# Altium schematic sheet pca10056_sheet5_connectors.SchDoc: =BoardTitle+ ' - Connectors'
size A3; Organization: Nordic Semiconductor; DocumentNumber: 5; SheetNumber: 5; SheetTotal: 6; CompanyName: Nordic Semiconductor; DocumentSize: A3
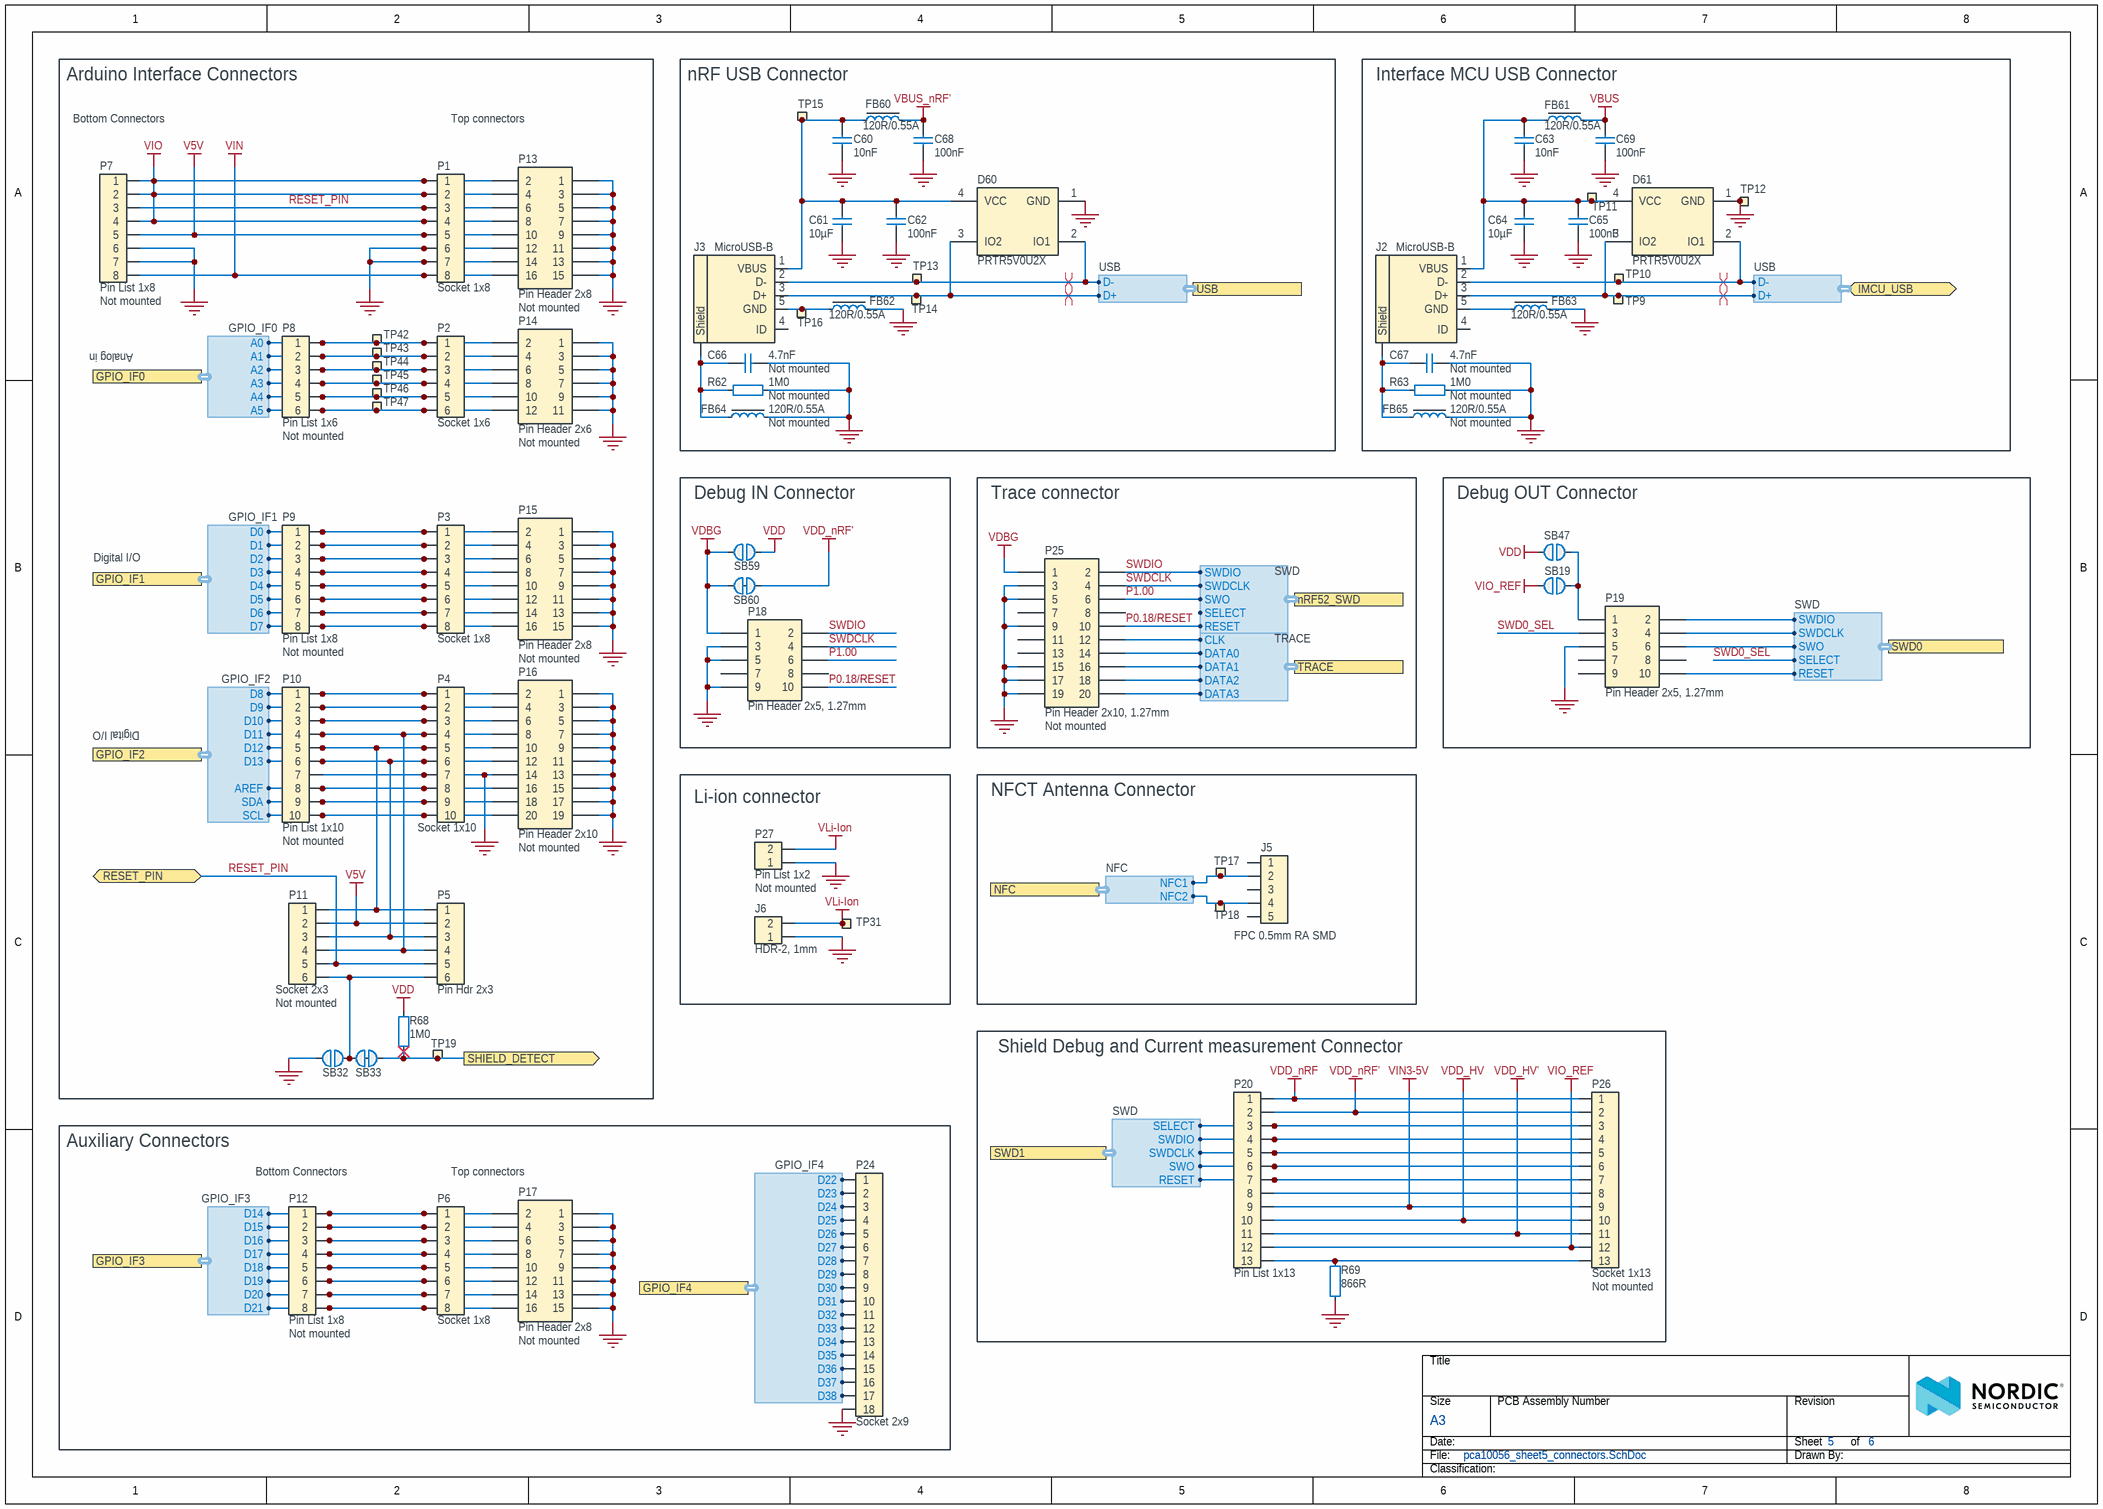
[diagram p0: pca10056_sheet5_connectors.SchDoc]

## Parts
C60  10nF  [CAPC0603X03L_C]
C61  10µF  [CAPC1608X06L]
C62  100nF  [CAPC0603X03L_C]
C63  10nF  [CAPC0603X03L_C]
C64  10µF  [CAPC1608X06L]
C65  100nF  [CAPC0603X03L_C]
C66  4.7nF  Assembly: Not mounted  [CAPC0603X03L_C]
C67  4.7nF  Assembly: Not mounted  [CAPC0603X03L_C]
C68  100nF  [CAPC0603X03L_C]
C69  100nF  [CAPC0603X03L_C]
D60  PRTR5V0U2X  [SOT190P230X110-4L]
D61  PRTR5V0U2X  [SOT190P230X110-4L]
FB60  120R/0.55A  [INDC1005X04L]
FB61  120R/0.55A  [INDC1005X04L]
FB62  120R/0.55A  [INDC1005X04L]
FB63  120R/0.55A  [INDC1005X04L]
FB64  120R/0.55A  Assembly: Not mounted  [INDC1005X04L]
FB65  120R/0.55A  Assembly: Not mounted  [INDC1005X04L]
J2  MicroUSB-B  [USB-Micro-B-RA-SMD-PiP_Allen]
J3  MicroUSB-B  [USB-Micro-B-RA-SMD-PiP_Allen]
J5  FPC 0.5mm RA SMD  [FPC_05P-0.5mm-RA-SMD]
J6  HDR-2, 1mm  [SM02B-SRSS-TB]
P1  Socket 1x8  [SOCKET_1x8_SMD]
P2  Socket 1x6  [SOCKET_1x6_SMD]
P3  Socket 1x8  [SOCKET_1x8_SMD]
P4  Socket 1x10  [SOCKET_1x10_SMD]
P5  Pin Hdr 2x3  [HDR_2x3-SMD]
P6  Socket 1x8  [SOCKET_1x8_SMD]
P7  Pin List 1x8  Assembly: Not mounted  [LIST_1x8_SMD-NC]
P8  Pin List 1x6  Assembly: Not mounted  [LIST_1x6_SMD-NC]
P9  Pin List 1x8  Assembly: Not mounted  [LIST_1x8_SMD-NC]
P10  Pin List 1x10  Assembly: Not mounted  [LIST_1x10_SMD-NC]
P11  Socket 2x3  Assembly: Not mounted  [SOCKET_2x3_SMD-2.54mm-NC]
P12  Pin List 1x8  Assembly: Not mounted  [LIST_1x8_SMD-NC]
P13  Pin Header 2x8  Assembly: Not mounted  [HDR_2x8-NC]
P14  Pin Header 2x6  Assembly: Not mounted  [HDR_2x6-NC]
P15  Pin Header 2x8  Assembly: Not mounted  [HDR_2x8-NC]
P16  Pin Header 2x10  Assembly: Not mounted  [HDR_2x10-NC]
P17  Pin Header 2x8  Assembly: Not mounted  [HDR_2x8-NC]
P18  Pin Header 2x5, 1.27mm  [HDR_2x5-SMD-1.27mm-K]
P19  Pin Header 2x5, 1.27mm  [HDR_2x5-SMD-1.27mm-K]
P20  Pin List 1x13  [LIST_1x13_SMD]
P24  Socket 2x9  [SOCKET_2x9_SMD-2.54mm-Mirrored]
P25  Pin Header 2x10, 1.27mm  Assembly: Not mounted  [HDR_2x10-SMD-1.27mm-NC]
P26  Socket 1x13  Assembly: Not mounted  [LIST_1x13_SMD-NC]
P27  Pin List 1x2  Assembly: Not mounted  [LIST_1x2-NC]
R62  1M0  Assembly: Not mounted  [RESC0603X03L_C]
R63  1M0  Assembly: Not mounted  [RESC0603X03L_C]
R68  1M0  [RESC0603X03L_C]
R69  866R  [RESC0603X03L_C]
SB19  Solderbridge  [Solderbridge]  (value not drawn)  (no BOM)
SB32  Solderbridge  [Solderbridge]  (value not drawn)  (no BOM)
SB33  Solderbridge  [Solderbridge_Shorted]  (value not drawn)  (net tie, no BOM)
SB47  Solderbridge  [Solderbridge]  (value not drawn)  (no BOM)
SB59  Solderbridge  [Solderbridge]  (value not drawn)  (no BOM)
SB60  Solderbridge  [Solderbridge_Shorted]  (value not drawn)  (net tie, no BOM)
TP9  Ø1.0mm,SMD  [TP_SMD_D1.0mm]  (value not drawn)  (no BOM)
TP10  Ø1.0mm,SMD  [TP_SMD_D1.0mm]  (value not drawn)  (no BOM)
TP11  Ø1.0mm,SMD  [TP_SMD_D1.0mm]  (value not drawn)  (no BOM)
TP12  Ø1.0mm,SMD  [TP_SMD_D1.0mm]  (value not drawn)  (no BOM)
TP13  Ø1.5mm,SMD  [TP_SMD_D1.5mm]  (value not drawn)  (no BOM)
TP14  Ø1.5mm,SMD  [TP_SMD_D1.5mm]  (value not drawn)  (no BOM)
TP15  Ø1.5mm,SMD  [TP_SMD_D1.5mm]  (value not drawn)  (no BOM)
TP16  Ø1.5mm,SMD  [TP_SMD_D1.5mm]  (value not drawn)  (no BOM)
TP17  Ø1.0mm,SMD  [TP_SMD_D1.0mm]  (value not drawn)  (no BOM)
TP18  Ø1.0mm,SMD  [TP_SMD_D1.0mm]  (value not drawn)  (no BOM)
TP19  Ø1.0mm,SMD  [TP_SMD_D1.0mm]  (value not drawn)  (no BOM)
TP31  Ø1.0mm,SMD  [TP_SMD_D1.0mm]  (value not drawn)  (no BOM)
TP42  Ø1.0mm,SMD  [TP_SMD_D1.0mm]  (value not drawn)  (no BOM)
TP43  Ø1.0mm,SMD  [TP_SMD_D1.0mm]  (value not drawn)  (no BOM)
TP44  Ø1.0mm,SMD  [TP_SMD_D1.0mm]  (value not drawn)  (no BOM)
TP45  Ø1.0mm,SMD  [TP_SMD_D1.0mm]  (value not drawn)  (no BOM)
TP46  Ø1.0mm,SMD  [TP_SMD_D1.0mm]  (value not drawn)  (no BOM)
TP47  Ø1.0mm,SMD  [TP_SMD_D1.0mm]  (value not drawn)  (no BOM)

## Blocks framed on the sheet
Arduino Interface Connectors: P1-P5 P7-P11 P13-P16 R68 SB32 SB33 TP19 TP42-TP47
nRF USB Connector: C60-C62 C66 C68 D60 FB60 FB62 FB64 J3 R62 TP13-TP16
Interface MCU USB Connector: C63-C65 C67 C69 D61 FB61 FB63 FB65 J2 R63 TP9-TP12
Debug IN Connector: P18 SB59 SB60
Trace connector: P25
Debug OUT Connector: P19 SB19 SB47
Li-ion connector: J6 P27 TP31
NFCT Antenna Connector: J5 TP17 TP18
Shield Debug and Current measurement Connector: P20 P26 R69
Auxiliary Connectors: P6 P12 P17 P24

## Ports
GPIO_IF0 (harness GPIO_IF0), GPIO_IF1 (harness GPIO_IF1), GPIO_IF2 (harness GPIO_IF2), GPIO_IF3 (harness GPIO_IF3), GPIO_IF4 (harness GPIO_IF4), IMCU_USB (bidir, harness USB), NFC (harness NFC), nRF52_SWD (harness SWD), RESET_PIN (bidir), SHIELD_DETECT (out), SWD0 (harness SWD), SWD1 (harness SWD), TRACE (harness TRACE), USB (harness USB)

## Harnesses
USB: D-, D+
USB: D+, D-
SWD: SWDIO, SWDCLK, SWO, RESET, SELECT
TRACE: CLK, DATA0, DATA1, DATA3, DATA2
NFC: NFC2, NFC1
GPIO_IF4: D22, D23, D24, D25, D26, D27, D28, D29, D30, D31, D32, D33, D34, D35, D36, D37, D38
GPIO_IF3: D14, D15, D16, D17, D18, D19, D20, D21
GPIO_IF1: D0, D1, D2, D3, D4, D5, D6, D7
GPIO_IF2: D8, D9, D10, D11, D12, D13, AREF, SDA, SCL
GPIO_IF0: A0, A1, A2, A3, A4, A5

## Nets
GND: C60.1 C61.1 C62.1 C63.2 C64.1 C65.1 C66.1 C67.1 C68.1 C69.1 D60.1(GND) D61.1(GND) FB62.2 FB63.2 FB64.2 FB65.2 J6.1 P1.6 P1.7 P4.7 P7.6 P7.7 P10.7 P13.1 P13.3 P13.5 P13.7 P13.9 P13.11 P13.12 P13.13 P13.14 P13.15 P14.1 P14.3 P14.5 P14.7 P14.9 P14.11 P15.1 P15.3 P15.5 P15.7 P15.9 P15.11 P15.13 P15.15 P16.1 P16.3 P16.5 P16.7 P16.9 P16.11 P16.13 P16.14 P16.15 P16.17 P16.19 P17.1 P17.3 P17.5 P17.7 P17.9 P17.11 P17.13 P17.15 P18.3 P18.5 P18.9 P19.5 P24.18 P25.3 P25.5 P25.9 P25.15 P25.17 P25.19 P27.1 R62.1 R63.1 R69.1 SB32.1 TP12.1
V5V: P1.5 P5.2 P7.5 P11.2 P13.10
VBUS: C69.2 FB61.2
VBUS_nRF': C68.2 FB60.2
VDBG: P18.1 P25.1 SB59.1 SB60.1
VDD: R68.2 SB47.1 SB59.2
VDD_HV: P20.10 P26.10
VDD_HV': P20.11 P26.11
VDD_nRF: P20.1 P26.1
VDD_nRF': P20.2 P26.2 SB60.2
VIN: P1.8 P7.8 P13.16
VIN3-5V: P20.9 P26.9
VIO: P1.1 P1.2 P1.4 P7.1 P7.2 P7.4 P13.2 P13.4 P13.8
VIO_REF: P20.12 P26.12 SB19.2
VLi-Ion: J6.2 P27.2 TP31.1
P0.18/RESET: P18.10 P25.10 ; port nRF52_SWD.RESET
P1.00: P18.6 P25.6 ; port nRF52_SWD.SWO
RESET_PIN: P1.3 P5.5 P7.3 P11.5 P13.6 ; port RESET_PIN
SHIELD_DETECT: R68.1 SB33.2 TP19.1 ; port SHIELD_DETECT
SWD0_SEL: P19.3 ; port SWD0.SELECT
SWDCLK: P18.4 P25.4 ; port nRF52_SWD.SWDCLK
SWDIO: P18.2 P25.2 ; port nRF52_SWD.SWDIO
NetC60_2: C60.2 C61.2 C62.2 D60.4(VCC) FB60.1 J3.1(VBUS) TP15.1
NetC63_1: C63.1 C64.2 C65.2 D61.4(VCC) FB61.1 J2.1(VBUS) TP11.1
NetC66_2: C66.2 FB64.1 J3.6(Shield) R62.2
NetC67_2: C67.2 FB65.1 J2.6(Shield) R63.2
NetD60_2: D60.2(IO1) J3.2(D-) TP13.1 ; port USB.D-
NetD60_3: D60.3(IO2) J3.3(D+) TP14.1 ; port USB.D+
NetD61_2: D61.2(IO1) J2.2(D-) TP10.1 ; port IMCU_USB.D-
NetD61_3: D61.3(IO2) J2.3(D+) TP9.1 ; port IMCU_USB.D+
NetFB62_1: FB62.1 J3.5(GND) TP16.1
NetFB63_1: FB63.1 J2.5(GND)
NetJ5_2: J5.2 TP17.1 ; port NFC.NFC1
NetJ5_4: J5.4 TP18.1 ; port NFC.NFC2
NetP2_1: P2.1 P8.1 P14.2 TP42.1 ; port GPIO_IF0.A0
NetP2_2: P2.2 P8.2 P14.4 TP43.1 ; port GPIO_IF0.A1
NetP2_3: P2.3 P8.3 P14.6 TP44.1 ; port GPIO_IF0.A2
NetP2_4: P2.4 P8.4 P14.8 TP45.1 ; port GPIO_IF0.A3
NetP2_5: P2.5 P8.5 P14.10 TP46.1 ; port GPIO_IF0.A4
NetP2_6: P2.6 P8.6 P14.12 TP47.1 ; port GPIO_IF0.A5
NetP3_1: P3.1 P9.1 P15.2 ; port GPIO_IF1.D0
NetP3_2: P3.2 P9.2 P15.4 ; port GPIO_IF1.D1
NetP3_3: P3.3 P9.3 P15.6 ; port GPIO_IF1.D2
NetP3_4: P3.4 P9.4 P15.8 ; port GPIO_IF1.D3
NetP3_5: P3.5 P9.5 P15.10 ; port GPIO_IF1.D4
NetP3_6: P3.6 P9.6 P15.12 ; port GPIO_IF1.D5
NetP3_7: P3.7 P9.7 P15.14 ; port GPIO_IF1.D6
NetP3_8: P3.8 P9.8 P15.16 ; port GPIO_IF1.D7
NetP4_1: P4.1 P10.1 P16.2 ; port GPIO_IF2.D8
NetP4_2: P4.2 P10.2 P16.4 ; port GPIO_IF2.D9
NetP4_3: P4.3 P10.3 P16.6 ; port GPIO_IF2.D10
NetP4_4: P4.4 P5.4 P10.4 P11.4 P16.8 ; port GPIO_IF2.D11
NetP4_5: P4.5 P5.1 P10.5 P11.1 P16.10 ; port GPIO_IF2.D12
NetP4_6: P4.6 P5.3 P10.6 P11.3 P16.12 ; port GPIO_IF2.D13
NetP4_8: P4.8 P10.8 P16.16 ; port GPIO_IF2.AREF
NetP4_9: P4.9 P10.9 P16.18 ; port GPIO_IF2.SDA
NetP4_10: P4.10 P10.10 P16.20 ; port GPIO_IF2.SCL
NetP5_6: P5.6 P11.6 SB32.2 SB33.1
NetP6_1: P6.1 P12.1 P17.2 ; port GPIO_IF3.D14
NetP6_2: P6.2 P12.2 P17.4 ; port GPIO_IF3.D15
NetP6_3: P6.3 P12.3 P17.6 ; port GPIO_IF3.D16
NetP6_4: P6.4 P12.4 P17.8 ; port GPIO_IF3.D17
NetP6_5: P6.5 P12.5 P17.10 ; port GPIO_IF3.D18
NetP6_6: P6.6 P12.6 P17.12 ; port GPIO_IF3.D19
NetP6_7: P6.7 P12.7 P17.14 ; port GPIO_IF3.D20
NetP6_8: P6.8 P12.8 P17.16 ; port GPIO_IF3.D21
NetP19_1: P19.1 SB19.1 SB47.2
NetP19_2: P19.2 ; port SWD0.SWDIO
NetP19_4: P19.4 ; port SWD0.SWDCLK
NetP19_6: P19.6 ; port SWD0.SWO
NetP19_10: P19.10 ; port SWD0.RESET
NetP20_3: P20.3 P26.3 ; port SWD1.SELECT
NetP20_4: P20.4 P26.4 ; port SWD1.SWDIO
NetP20_5: P20.5 P26.5 ; port SWD1.SWDCLK
NetP20_6: P20.6 P26.6 ; port SWD1.SWO
NetP20_7: P20.7 P26.7 ; port SWD1.RESET
NetP20_8: P20.8 P26.8
NetP20_13: P20.13 P26.13 R69.2
NetP24_1: P24.1 ; port GPIO_IF4.D22
NetP24_2: P24.2 ; port GPIO_IF4.D23
NetP24_3: P24.3 ; port GPIO_IF4.D24
NetP24_4: P24.4 ; port GPIO_IF4.D25
NetP24_5: P24.5 ; port GPIO_IF4.D26
NetP24_6: P24.6 ; port GPIO_IF4.D27
NetP24_7: P24.7 ; port GPIO_IF4.D28
NetP24_8: P24.8 ; port GPIO_IF4.D29
NetP24_9: P24.9 ; port GPIO_IF4.D30
NetP24_10: P24.10 ; port GPIO_IF4.D31
NetP24_11: P24.11 ; port GPIO_IF4.D32
NetP24_12: P24.12 ; port GPIO_IF4.D33
NetP24_13: P24.13 ; port GPIO_IF4.D34
NetP24_14: P24.14 ; port GPIO_IF4.D35
NetP24_15: P24.15 ; port GPIO_IF4.D36
NetP24_16: P24.16 ; port GPIO_IF4.D37
NetP24_17: P24.17 ; port GPIO_IF4.D38
NetP25_12: P25.12 ; port TRACE.CLK
NetP25_14: P25.14 ; port TRACE.DATA0
NetP25_16: P25.16 ; port TRACE.DATA1
NetP25_18: P25.18 ; port TRACE.DATA2
NetP25_20: P25.20 ; port TRACE.DATA3

Not connected (* = marked no-connect by the designer): J2 4(ID); J3 4(ID); J5 1 3 5; P18 7 8; P19 7 8 9; P25 7 8 11 13

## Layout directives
differential pair: NetD60_2, NetD60_3, NetD61_2, NetD61_3

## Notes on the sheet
- Bottom Connectors
- Top connectors
- Analog in
- Digital I/O
- (near P12) Bottom Connectors

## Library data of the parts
C60 C63 = C0201-10n: Capacitor, X7R, ±10%; Manufacturer: N.A.; Part number IPS: 00000003480; Part number Norautron: 26621779; Part number NEMS: 100200067; Note: 10V; Pad Count: 2; Component Status: Active
C61 C64 = C0603-10µ: Capacitor, X5R, ±20%; Manufacturer: N.A.; Part number IPS: 00000007785; Part number NEMS: 100200275; Note: 6.3V; Artikkelnr Noca: 20039234; Pad Count: 2; Component Status: Active
C62 C65 C68 C69 = C0201-100n: Capacitor, X5R, ±10%; Manufacturer: N.A.; Part number IPS: 00000001248, 00000002505; Part number Norautron: 262071862; Part number NEMS: 100200078; Note: 16V; Pad Count: 2; Component Status: Active
C66 C67 = C0201-4n7: Capacitor, X7R, ±10%, 10V; Manufacturer: N.A.; Part number IPS: 00000001243; Part number NEMS: 100200063; Note: Chip Cap 1%; Pad Count: 2; Component Status: Active
D60 D61 = PRTR5V0U2X: Ultra low capacitance double rail-to-rail ESD protection diode; Manufacturer: NXP Semiconductors; Part number IPS: 00000009951; Part number Norautron: 26313940; Part number NEMS: 101300082; Note: N.A.; Artikkelnr Noca: 10069015; Pad Count: 4; Component Status: Active
FB60-FB65 = FB0402-120R@100M-500mA: Ferrite Bead, 120 Ohm @ 100MHz, 500mA, 250 mOhm Max; Manufacturer: Murata; Manufacturer Part Number: BLM15AG121SN1D; Part number IPS: 00000009954; Part number Norautron: 265230631; Part number NEMS: 100300099; Note: Chip EMIFIL Inductor Type Chip Ferrite Bead; Artikkelnr Noca: 33029317; Pad Count: 2; Component Status: Active
J2 J3 = USB-Micro-B-RA-SMD-PiP: MicroUSB-B-SMT; Manufacturer: Allen Creations Corp.; Manufacturer Part Number: AJU55-BS2111-L; Part number IPS: 00000007790; Part number NEMS: 100500490; Note: N.A.; Pad Count: 9; Component Status: Active; System: Connector
J5 = FPC_05P-0.5mm-RA-SMD: 0.5mm FPC, 5P,Right Angle SMT,Double Contact,H=1.2mm,White, Tin plated; Manufacturer: WCON; Manufacturer Part Number: 5141-05RZDNWR03; Part number NEMS: 100500528; Note: (Replaced 5141-05RZDNWR02); Artikkelnr Noca: N.A.; Pad Count: 7; Component Status: Active; System: Connector
J6 = SM02B-SRSS-TB: 1.0mm pitch connector side entry SMD; Manufacturer: JST Sales America Inc.; Manufacturer Part Number: SM02B-SRSS-TB(LF)(SN); Part number IPS: 00000007791; Part number Norautron: N.A.; Part number NEMS: 100500383; Note: JST, Header; Artikkelnr Noca: 55010030; Pad Count: 2; Component Status: Active
P1 P3 P6 = Socket 1x8 SMD: Socket 1x8, 2.54mm (100mil), SMD; Manufacturer: WCON; Manufacturer Part Number: 2171-108MS0CUNR3; Part number NEMS: 100500412; Note: (Replaced 2171-108MS0CUNR1); Artikkelnr Noca: N.A.; Pad Count: 8; Component Status: Active; System: Connector
P2 = Socket 1x6 SMD: Socket 1x6, 2.54mm (100mil), SMD; Manufacturer: WCON; Manufacturer Part Number: 2171-106MS0CUNR3; Part number NEMS: 100500408; Note: (Replaced 2171-106MS0CUNR1); Artikkelnr Noca: N.A.; Pad Count: 6; Component Status: Active; System: Connector
P4 = Socket 1x10 SMD: Socket 1x10, 2.54mm (100mil), SMD; Manufacturer: WCON; Manufacturer Part Number: 2171-110MS0CUNR3; Part number NEMS: 100500416; Note: (Replaced 2171-110MS0CUNR1); Artikkelnr Noca: N.A.; Pad Count: 10; Component Status: Active; System: Connector
P5 = Pin Header 2x3 SMD: Pin Header 2x3, 2.54mm (100mil) SMD; Manufacturer: WCON; Manufacturer Part Number: 1125-1203S0M116CR03; Part number NEMS: 100500242; Note: (Replaced 1125-1203S0M116CR03); Artikkelnr Noca: N.A.; Pad Count: 6; Component Status: Active; System: Connector
P7 P9 P12 = Pin List 1x8 SMD, N.C.: Pin List 1x8, 2.54mm (100mil), SMD; Manufacturer: WCON; Manufacturer Part Number: 1125-1108S0M116CR04; Part number NEMS: 100500330; Note: (Replaced 1125-1108S0M116R2); Artikkelnr Noca: N.A.; Pad Count: 8; Component Status: Active; System: Connector
P8 = Pin List 1x6 SMD, N.C.: Pin List 1x6, 2.54mm (100mil), SMD; Manufacturer: WCON; Manufacturer Part Number: 1125-1106S0M116R2; Part number NEMS: 100500321; Note: N.A.; Artikkelnr Noca: 55010026; Pad Count: 6; Component Status: Active; System: Connector
P10 = Pin List 1x10 SMD, N.C.: Pin List 1x10, 2.54mm (100mil), SMD; Manufacturer: WCON; Manufacturer Part Number: 1125-1110S0M116R2; Part number NEMS: 100500338; Note: N.A.; Artikkelnr Noca: 55010028; Pad Count: 10; Component Status: Active; System: Connector
P11 = Socket 2x3 SMD, N.C.: Socket 2x3, 2.54mm (100mil), SMD; Manufacturer: WCON; Manufacturer Part Number: 2171-203MS0CUNR3; Part number NEMS: 100500434; Note: (Replaced 2171-203MS0CUNR1); Artikkelnr Noca: N.A.; Pad Count: 6; Component Status: Active; System: Connector
P13 P15 P17 = Pin Header 2x8, N.C.: Pin Header 2x8, 2.54mm (100mil); Manufacturer: N.A.; Part number NEMS: 100500270; Pad Count: 16; Component Status: Active; System: Connector
P14 = Pin Header 2x6, N.C.: Pin Header 2x6, 2.54mm (100mil); Manufacturer: N.A.; Part number NEMS: 100500265; Pad Count: 12; Component Status: Active; System: Connector
P16 = Pin Header 2x10, N.C.: Pin Header 2x10, 2.54mm (100mil); Manufacturer: N.A.; Part number NEMS: 100500274; Pad Count: 20; Component Status: Active; System: Connector
P18 P19 = Pin Header 2x5 SMD, 1.27mm, KS: Pin Header 2x5, 1.27mm (50mil), SMD, Keying Shroud; Manufacturer: WCON; Manufacturer Part Number: 3132-10MS0BK00R5; Part number NEMS: 100500261; Note: (Replaced 3132-10MS0BK00R1); Artikkelnr Noca: N.A.; Pad Count: 10; Component Status: Active; System: Connector
P20 = Pin List 1x13 SMD: Pin List 1x13, 2.54mm (100mil), SMD; Manufacturer: WCON; Manufacturer Part Number: 1125-1113S0M116CR04; Part number NEMS: 100500345; Note: (Replaced 1125-1113S0M116R2); Artikkelnr Noca: N.A.; Pad Count: 13; Component Status: Active; System: Connector
P24 = Socket 2x9 SMD: Socket 2x9, 2.54mm (100mil), SMD; Manufacturer: WCON; Manufacturer Part Number: 2171-209MS0CUNR3; Part number NEMS: 100500440; Note: (Replaced 2171-209MS0CUNR1); Artikkelnr Noca: N.A.; Pad Count: 18; Component Status: Active; System: Connector
P25 = Pin Header 2x10 SMD, 1.27mm, KS, N.C.: Pin Header 2x10, 1.27mm (50mil), SMD, Keying Shroud; Manufacturer: WCON; Manufacturer Part Number: 3132-20MS0BK00R1; Part number NEMS: 100500279; Note: N.A.; Pad Count: 20; Component Status: Active; System: Connector
P26 = Socket 1x13 SMD, N.C.: Socket 1x13, 2.54mm (100mil), SMD; Manufacturer: WCON; Manufacturer Part Number: 2171-113MS0CUNR1; Part number NEMS: 100500422; Note: N.A.; Pad Count: 13; Component Status: Active; System: Connector
P27 = Pin List 1x2, N.C.: Pin List 1x2, 2.54mm (100mil); Manufacturer: N.A.; Part number NEMS: 100500298; Pad Count: 2; Component Status: Active; System: Connector
R62 R63 R68 = R0201-1M0: Resistor, ±1%, 0.05W; Manufacturer: N.A.; Part number IPS: 00000001418; Part number Norautron: 26107108; Part number NEMS: 100100093; Note: Chip Res 1%; Pad Count: 2; Component Status: Active
R69 = R0201-866: Resistor, ±1%, 0.05W; Manufacturer: N.A.; Part number IPS: 00000004368; Part number NEMS: 100100042; Note: Chip Res 1%; Pad Count: 2; Component Status: Active
SB19 SB32 SB47 SB59 = Solderbridge: Manufacturer: N.A.; Part number NEMS: 100500458; Pad Count: 2; Component Status: Active; System: Connector
SB33 SB60 = Solderbridge Shorted: Shorted Solderbridge; Manufacturer: N.A.; Part number NEMS: 100500459; Pad Count: 2; Component Status: Active; System: Connector
TP9-TP12 TP17-TP19 TP31 TP42-TP47 = TP_SMD_Ø1.0MM: 1.0mm circular SMD testpad; Manufacturer: Nordic Semiconductor; Manufacturer Part Number: N.A.; Part number NEMS: 100500475; Pad Count: 1; Component Status: Active
TP13-TP16 = TP_SMD_Ø1.5MM: 1.5mm circular SMD testpad; Manufacturer: Nordic Semiconductor; Manufacturer Part Number: N.A.; Part number NEMS: 100500477; Pad Count: 1; Component Status: Active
